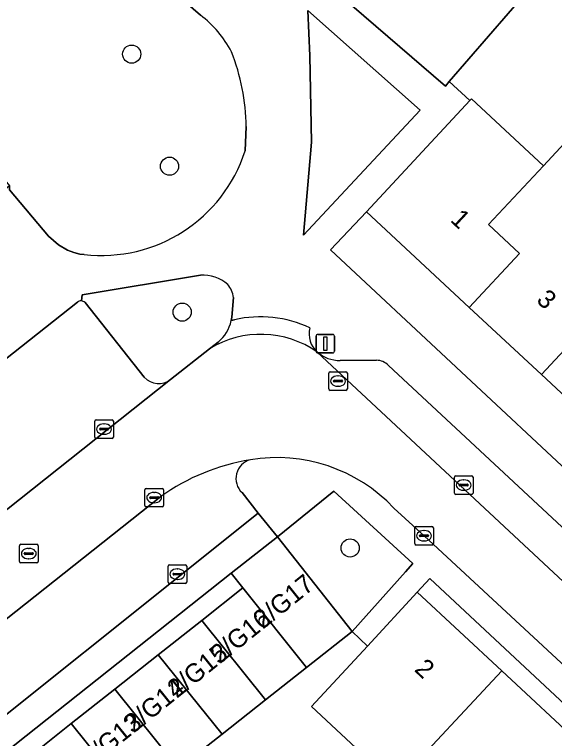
# Model space of a CAD drawing. Extents: x 162344 to 162869, y 381217 to 381818.
# Drawn here: x 162525.97 to 162555.05, y 381693.96 to 381732.95 of the extents above; entities that cross this region are included whole.
import ezdxf

# ---------------------------------------------------------------- set-up
doc = ezdxf.new("R2010")
doc.units = 0
for name, color, linetype in [('IMGEO_Boom', 7, 'Continuous'), ('IMGEO_Erf', 7, 'Continuous'), ('IMGEO_Groenvoorziening', 7, 'Continuous'), ('IMGEO_Kolk', 7, 'Continuous'), ('IMGEO_Lichtmast', 7, 'Continuous'), ('IMGEO_Pand', 7, 'Continuous'), ('IMGEO_Pand_nummerreeks', 7, 'Continuous'), ('IMGEO_Parkeervlak_open', 7, 'Continuous'), ('IMGEO_Rijbaan_lokaal_open', 7, 'Continuous'), ('IMGEO_Rioolput', 7, 'Continuous'), ('IMGEO_Voetpad_open', 7, 'Continuous')]:
    doc.layers.add(name, color=color, linetype=linetype)

msp = doc.modelspace()

# ---------------------------------------------------------------- linework, layer by layer
at = {"layer": 'IMGEO_Boom'}
for centre in [(162532.281, 381730.813), (162534.318, 381724.778), (162535, 381716.921), (162544.045, 381704.221)]:
    msp.add_circle(centre, 0.489, dxfattribs=at)
at = {"layer": 'IMGEO_Erf'}
for points in [[(162535.988, 381732.91), (162527.407, 381740.337), (162531.519, 381745.279), (162534.788, 381749.063), (162535.324, 381749.683), (162537.606, 381747.769), (162539.888, 381745.856), (162542.17, 381743.942), (162544.451, 381742.029), (162546.664, 381740.173), (162550.954, 381736.576), (162551.92, 381735.702), (162553.619, 381734.234), (162549.382, 381729.332), (162550.499, 381728.32), (162550.577, 381728.404), (162554.45, 381724.8), (162556.476, 381726.97)], [(162512.168, 381740.102), (162518.981, 381731.851), (162525.696, 381723.717), (162525.707, 381723.511), (162527.801, 381721.016), (162528.341, 381720.543), (162528.826, 381720.252), (162529.167, 381720.123), (162529.489, 381720.046), (162529.724, 381720.026)], [(162538.393, 381725.598), (162538.45, 381726.908)], [(162558.088, 381710.077), (162554.346, 381713.559), (162550.459, 381717.175), (162544.927, 381722.323), (162542.992, 381720.281), (162563.297, 381701.321)], [(162555.476, 381683.106), (162550.927, 381687.341), (162546.49, 381691.473), (162541.97, 381695.681), (162544.973, 381698.927), (162544.148, 381699.726), (162541.703, 381697.791), (162539.492, 381696.043), (162537.149, 381694.189), (162535.306, 381692.731), (162538.276, 381689.5), (162539.852, 381690.979), (162542.943, 381687.685), (162546.276, 381684.134), (162544.711, 381682.665), (162546.747, 381680.449), (162548.3, 381681.923), (162551.41, 381678.647), (162554.71, 381675.17), (162553.057, 381673.602), (162555.205, 381671.414)]]:
    msp.add_lwpolyline(points, dxfattribs=at)
for points in [[(162533.709, 381698.468), (162536.051, 381700.322), (162538.262, 381702.071), (162537.642, 381702.856), (162523.799, 381691.897), (162524.422, 381691.121), (162526.68, 381692.908), (162529.023, 381694.761), (162531.366, 381696.615)], [(162548.344, 381702.569), (162547.662, 381701.832), (162552.208, 381697.599), (162556.645, 381693.468), (162561.194, 381689.233), (162565.777, 381684.966), (162570.32, 381680.736), (162574.872, 381676.499), (162579.382, 381672.299), (162583.891, 381668.101), (162588.442, 381663.864), (162592.919, 381659.696), (162597.312, 381655.606), (162601.823, 381651.406), (162606.458, 381647.09), (162610.852, 381643), (162615.546, 381638.629), (162616.162, 381639.291), (162606.523, 381648.285)]]:
    msp.add_lwpolyline(points, close=True, dxfattribs=at)
for centre, radius, start, end in [((162532.255, 381728.039), 6.137, 28.2561, 52.5372), ((162526.473, 381726.662), 11.98, 1.1781, 20.9444), ((162530.655, 381728.107), 8.134, 263.4255, 342.0363)]:
    msp.add_arc(centre, radius, start, end, dxfattribs=at)
at = {"layer": 'IMGEO_Groenvoorziening'}
for points in [[(162547.81, 381727.798), (162541.758, 381733.154), (162541.879, 381730.723), (162541.969, 381726.066), (162541.541, 381721.067)], [(162543.164, 381707.283), (162540.132, 381704.823), (162544.148, 381699.726), (162547.035, 381702.94), (162547.422, 381703.385)]]:
    msp.add_lwpolyline(points, close=True, dxfattribs=at)
for points in [[(162535.987, 381718.904), (162529.615, 381717.858), (162529.568, 381717.524)], [(162537.637, 381716.462), (162537.667, 381716.641), (162537.757, 381717.705)], [(162529.766, 381717.44), (162532.959, 381713.412)], [(162534.376, 381713.298), (162536.476, 381714.949), (162536.94, 381715.31)]]:
    msp.add_lwpolyline(points, dxfattribs=at)
for centre, radius, start, end in [((162536.131, 381716.917), 1.992, 48.5378, 94.1464), ((162536.467, 381717.563), 1.298, 6.2969, 40.7656), ((162529.556, 381717.221), 0.303, 46.2549, 87.7676), ((162535.642, 381716.882), 2.038, 309.5387, 348.1105), ((162533.73, 381714.127), 1.051, 222.8426, 307.9582)]:
    msp.add_arc(centre, radius, start, end, dxfattribs=at)
at = {"layer": 'IMGEO_Kolk'}
for p, q in [((162530.293, 381710.194), (162530.293, 381711.046)), ((162530.368, 381711.12), (162531.22, 381711.12)), ((162530.781, 381710.9), (162530.806, 381710.9)), ((162531.294, 381711.046), (162531.294, 381710.194)), ((162530.552, 381710.614), (162530.552, 381710.626)), ((162530.99, 381710.577), (162530.592, 381710.577)), ((162530.595, 381710.663), (162530.993, 381710.663)), ((162531.036, 381710.626), (162531.036, 381710.614)), ((162531.22, 381710.12), (162530.368, 381710.12)), ((162530.804, 381710.34), (162530.779, 381710.34)), ((162549.661, 381707.18), (162549.661, 381708.032)), ((162549.736, 381708.106), (162550.588, 381708.106)), ((162550.149, 381707.886), (162550.174, 381707.886)), ((162550.662, 381708.032), (162550.662, 381707.18)), ((162533.066, 381707.431), (162533.918, 381707.431)), ((162549.92, 381707.6), (162549.92, 381707.612)), ((162550.358, 381707.563), (162549.96, 381707.563)), ((162549.963, 381707.649), (162550.361, 381707.649)), ((162550.404, 381707.612), (162550.404, 381707.6)), ((162532.991, 381706.505), (162532.991, 381707.357)), ((162533.479, 381707.211), (162533.504, 381707.211)), ((162533.992, 381707.357), (162533.992, 381706.505)), ((162550.588, 381707.106), (162549.736, 381707.106)), ((162550.172, 381707.326), (162550.147, 381707.326)), ((162533.25, 381706.925), (162533.25, 381706.937)), ((162533.688, 381706.888), (162533.29, 381706.888)), ((162533.293, 381706.974), (162533.691, 381706.974)), ((162533.502, 381706.651), (162533.477, 381706.651)), ((162533.734, 381706.937), (162533.734, 381706.925)), ((162533.918, 381706.431), (162533.066, 381706.431)), ((162547.526, 381704.453), (162547.526, 381705.305)), ((162547.601, 381705.379), (162548.453, 381705.379)), ((162548.014, 381705.159), (162548.039, 381705.159)), ((162548.527, 381705.305), (162548.527, 381704.453)), ((162547.785, 381704.873), (162547.785, 381704.885)), ((162548.223, 381704.836), (162547.825, 381704.836)), ((162547.828, 381704.922), (162548.226, 381704.922)), ((162548.269, 381704.885), (162548.269, 381704.873)), ((162548.453, 381704.379), (162547.601, 381704.379)), ((162548.037, 381704.599), (162548.012, 381704.599)), ((162534.243, 381702.384), (162534.243, 381703.236)), ((162534.318, 381703.31), (162535.17, 381703.31)), ((162535.244, 381703.236), (162535.244, 381702.384)), ((162534.502, 381702.804), (162534.502, 381702.816)), ((162534.94, 381702.767), (162534.542, 381702.767)), ((162534.545, 381702.853), (162534.943, 381702.853)), ((162534.731, 381703.09), (162534.756, 381703.09)), ((162534.986, 381702.816), (162534.986, 381702.804)), ((162534.754, 381702.53), (162534.729, 381702.53)), ((162535.17, 381702.31), (162534.318, 381702.31))]:
    msp.add_line(p, q, dxfattribs=at)
for points in [[(162530.293, 381710.194), (162530.293, 381711.046)], [(162530.368, 381711.12), (162531.22, 381711.12)], [(162531.294, 381711.046), (162531.294, 381710.194)], [(162531.22, 381710.12), (162530.368, 381710.12)], [(162549.661, 381707.18), (162549.661, 381708.032)], [(162549.736, 381708.106), (162550.588, 381708.106)], [(162550.662, 381708.032), (162550.662, 381707.18)], [(162533.066, 381707.431), (162533.918, 381707.431)], [(162532.991, 381706.505), (162532.991, 381707.357)], [(162533.992, 381707.357), (162533.992, 381706.505)], [(162550.588, 381707.106), (162549.736, 381707.106)], [(162533.918, 381706.431), (162533.066, 381706.431)], [(162547.526, 381704.453), (162547.526, 381705.305)], [(162547.601, 381705.379), (162548.453, 381705.379)], [(162548.527, 381705.305), (162548.527, 381704.453)], [(162548.453, 381704.379), (162547.601, 381704.379)], [(162534.243, 381702.384), (162534.243, 381703.236)], [(162534.318, 381703.31), (162535.17, 381703.31)], [(162535.244, 381703.236), (162535.244, 381702.384)], [(162535.17, 381702.31), (162534.318, 381702.31)]]:
    msp.add_lwpolyline(points, dxfattribs=at)
for centre, radius, start, end in [((162530.37, 381711.044), 0.0765, 91.552, 178.448), ((162530.37, 381711.044), 0.0765, 91.552, 178.448), ((162531.218, 381711.044), 0.0765, 1.552, 88.448), ((162531.218, 381711.044), 0.0765, 1.552, 88.448), ((162530.592, 381710.623), 0.0403, 85.8775, 175.7526), ((162530.589, 381710.613), 0.0366, 178.938, 274.7102), ((162530.993, 381710.62), 0.043, 264.8664, 352.4533), ((162530.997, 381710.625), 0.0386, 1.7309, 96.639), ((162530.37, 381710.196), 0.0765, 181.552, 268.448), ((162530.37, 381710.196), 0.0765, 181.552, 268.448), ((162531.218, 381710.196), 0.0765, 271.552, 358.448), ((162531.218, 381710.196), 0.0765, 271.552, 358.448), ((162549.738, 381708.03), 0.0765, 91.552, 178.448), ((162549.738, 381708.03), 0.0765, 91.552, 178.448), ((162550.586, 381708.03), 0.0765, 1.552, 88.448), ((162550.586, 381708.03), 0.0765, 1.552, 88.448), ((162533.068, 381707.355), 0.0765, 91.552, 178.448), ((162533.068, 381707.355), 0.0765, 91.552, 178.448), ((162533.916, 381707.355), 0.0765, 1.552, 88.448), ((162533.916, 381707.355), 0.0765, 1.552, 88.448), ((162549.96, 381707.609), 0.0403, 85.8775, 175.7526), ((162549.957, 381707.599), 0.0366, 178.938, 274.7102), ((162550.361, 381707.606), 0.043, 264.8664, 352.4533), ((162550.365, 381707.611), 0.0386, 1.7309, 96.639), ((162549.738, 381707.182), 0.0765, 181.552, 268.448), ((162549.738, 381707.182), 0.0765, 181.552, 268.448), ((162550.586, 381707.182), 0.0765, 271.552, 358.448), ((162550.586, 381707.182), 0.0765, 271.552, 358.448), ((162533.29, 381706.934), 0.0403, 85.8775, 175.7526), ((162533.287, 381706.924), 0.0366, 178.938, 274.7102), ((162533.691, 381706.931), 0.043, 264.8664, 352.4533), ((162533.695, 381706.936), 0.0386, 1.7309, 96.639), ((162533.068, 381706.507), 0.0765, 181.552, 268.448), ((162533.068, 381706.507), 0.0765, 181.552, 268.448), ((162533.916, 381706.507), 0.0765, 271.552, 358.448), ((162533.916, 381706.507), 0.0765, 271.552, 358.448), ((162547.603, 381705.303), 0.0765, 91.552, 178.448), ((162547.603, 381705.303), 0.0765, 91.552, 178.448), ((162548.451, 381705.303), 0.0765, 1.552, 88.448), ((162548.451, 381705.303), 0.0765, 1.552, 88.448), ((162547.825, 381704.882), 0.0403, 85.8775, 175.7526), ((162547.822, 381704.872), 0.0366, 178.938, 274.7102), ((162548.226, 381704.879), 0.043, 264.8664, 352.4533), ((162548.23, 381704.884), 0.0386, 1.7309, 96.639), ((162547.603, 381704.455), 0.0765, 181.552, 268.448), ((162547.603, 381704.455), 0.0765, 181.552, 268.448), ((162548.451, 381704.455), 0.0765, 271.552, 358.448), ((162548.451, 381704.455), 0.0765, 271.552, 358.448), ((162534.32, 381703.234), 0.0765, 91.552, 178.448), ((162534.32, 381703.234), 0.0765, 91.552, 178.448), ((162535.168, 381703.234), 0.0765, 1.552, 88.448), ((162535.168, 381703.234), 0.0765, 1.552, 88.448), ((162534.542, 381702.813), 0.0403, 85.8775, 175.7526), ((162534.539, 381702.803), 0.0366, 178.938, 274.7102), ((162534.943, 381702.81), 0.043, 264.8664, 352.4533), ((162534.947, 381702.815), 0.0386, 1.7309, 96.639), ((162534.32, 381702.386), 0.0765, 181.552, 268.448), ((162534.32, 381702.386), 0.0765, 181.552, 268.448), ((162535.168, 381702.386), 0.0765, 271.552, 358.448), ((162535.168, 381702.386), 0.0765, 271.552, 358.448)]:
    msp.add_arc(centre, radius, start, end, dxfattribs=at)
for centre, major_axis, ratio, start_param, end_param in [((162530.78, 381710.62), (-0.387, 0.002), 0.722429, 4.712389, 7.853982), ((162530.805, 381710.62), (-0.39, 0.002), 0.717154, 1.570796, 4.712389), ((162550.148, 381707.606), (-0.387, 0.002), 0.722429, 4.712389, 7.853982), ((162550.173, 381707.606), (-0.39, 0.002), 0.717154, 1.570796, 4.712389), ((162533.478, 381706.931), (-0.387, 0.002), 0.722429, 4.712389, 7.853982), ((162533.503, 381706.931), (-0.39, 0.002), 0.717154, 1.570796, 4.712389), ((162548.013, 381704.879), (-0.387, 0.002), 0.722429, 4.712389, 7.853982), ((162548.038, 381704.879), (-0.39, 0.002), 0.717154, 1.570796, 4.712389), ((162534.73, 381702.81), (-0.387, 0.002), 0.722429, 4.712389, 7.853982), ((162534.755, 381702.81), (-0.39, 0.002), 0.717154, 1.570796, 4.712389)]:
    msp.add_ellipse(centre, major_axis=major_axis, ratio=ratio, start_param=start_param, end_param=end_param, dxfattribs=at)
at = {"layer": 'IMGEO_Lichtmast'}
for p, q in [((162542.211, 381714.82), (162542.211, 381715.62)), ((162542.211, 381715.62), (162542.211, 381714.82)), ((162542.311, 381715.72), (162543.101, 381715.72)), ((162543.101, 381715.72), (162542.311, 381715.72)), ((162543.201, 381715.62), (162543.201, 381714.82)), ((162543.201, 381714.82), (162543.201, 381715.62)), ((162543.101, 381714.72), (162542.311, 381714.72)), ((162542.311, 381714.72), (162543.101, 381714.72))]:
    msp.add_line(p, q, dxfattribs=at)
msp.add_lwpolyline([(162542.631, 381715.595), (162542.781, 381715.595), (162542.781, 381714.845), (162542.631, 381714.845), (162542.631, 381715.595)], dxfattribs=at)
for centre, start, end in [((162542.311, 381715.62), 90, 180), ((162542.311, 381715.62), 90, 180), ((162543.101, 381715.62), 0, 90), ((162543.101, 381715.62), 360, 90), ((162542.311, 381714.82), 180, 270), ((162542.311, 381714.82), 180, 270), ((162543.101, 381714.82), 270, 0), ((162543.101, 381714.82), 270, 0)]:
    msp.add_arc(centre, 0.1, start, end, dxfattribs=at)
at = {"layer": 'IMGEO_Pand'}
for points in [[(162551.92, 381735.702), (162550.954, 381736.576), (162546.664, 381740.173), (162542.783, 381735.545), (162542.325, 381735.015), (162549.177, 381729.094), (162549.382, 381729.332), (162553.619, 381734.234)], [(162554.45, 381724.8), (162550.577, 381728.404), (162550.499, 381728.32), (162544.927, 381722.323), (162550.459, 381717.175), (162553.161, 381720.07), (162551.49, 381721.63)], [(162560.009, 381719.627), (162559.819, 381719.804), (162561.841, 381721.977), (162556.476, 381726.97), (162554.45, 381724.8), (162551.49, 381721.63), (162553.161, 381720.07), (162550.459, 381717.175), (162554.346, 381713.559)], [(162565.324, 381714.682), (162560.009, 381719.627), (162554.346, 381713.559), (162558.088, 381710.077), (162560.779, 381712.96), (162562.349, 381711.494)], [(162540.132, 381704.823), (162537.642, 381702.856), (162538.262, 381702.071), (162541.703, 381697.791), (162544.148, 381699.726)], [(162538.262, 381702.071), (162536.051, 381700.322), (162539.492, 381696.043), (162541.703, 381697.791)], [(162552.208, 381697.599), (162547.662, 381701.832), (162544.973, 381698.927), (162541.97, 381695.681), (162546.49, 381691.473)], [(162536.051, 381700.322), (162533.709, 381698.468), (162537.149, 381694.189), (162539.492, 381696.043)], [(162533.709, 381698.468), (162531.366, 381696.615), (162534.807, 381692.336), (162535.306, 381692.731), (162537.149, 381694.189)], [(162556.645, 381693.468), (162552.208, 381697.599), (162546.49, 381691.473), (162550.927, 381687.341)], [(162531.366, 381696.615), (162529.023, 381694.761), (162532.464, 381690.482), (162534.807, 381692.336)], [(162529.023, 381694.761), (162526.68, 381692.908), (162530.121, 381688.629), (162532.464, 381690.482)]]:
    msp.add_lwpolyline(points, close=True, dxfattribs=at)
at = {"layer": 'IMGEO_Parkeervlak_open'}
for points in [[(162529.359, 381717.448), (162521.93, 381711.58)], [(162532.959, 381713.412), (162529.766, 381717.44)], [(162542.273, 381714.77), (162580.185, 381679.418), (162591.19, 381669.184), (162593.726, 381666.826), (162618.042, 381644.213), (162632.252, 381630.976)], [(162545.457, 381714.327), (162543.509, 381714.316)], [(162581.635, 381680.986), (162546.116, 381714.053)], [(162524.911, 381705.794), (162534.376, 381713.298)], [(162533.842, 381706.991), (162517.7, 381694.186)], [(162539.084, 381706.089), (162538.222, 381707.201)], [(162517.937, 381694.149), (162520.357, 381691.127), (162539.084, 381706.089)]]:
    msp.add_lwpolyline(points, dxfattribs=at)
for centre, radius, start, end in [((162529.559, 381717.224), 0.3, 88.2365, 131.7297), ((162529.556, 381717.221), 0.303, 46.2549, 87.7676), ((162543.494, 381716.184), 1.868, 229.1905, 270.4715), ((162545.456, 381713.395), 0.932, 44.9144, 89.9323), ((162533.73, 381714.127), 1.051, 222.8426, 307.9582), ((162540.529, 381697.545), 11.574, 99.2428, 125.2941), ((162538.936, 381707.96), 1.042, 104.7779, 226.7685)]:
    msp.add_arc(centre, radius, start, end, dxfattribs=at)
at = {"layer": 'IMGEO_Rijbaan_lokaal_open'}
for points in [[(162536.476, 381714.949), (162534.376, 381713.298), (162524.911, 381705.794), (162522.199, 381703.639), (162499.727, 381685.849), (162498.226, 381684.626), (162498.069, 381684.526), (162479.74, 381669.953), (162476.682, 381667.526), (162476.099, 381667.062), (162478.985, 381663.489), (162479.173, 381663.648), (162479.827, 381664.177), (162479.911, 381664.241), (162502.297, 381681.971)], [(162546.399, 381706.372), (162548.027, 381704.879), (162560.818, 381693.021), (162573.453, 381681.241), (162574.275, 381680.474), (162586.238, 381669.332), (162588.969, 381666.789), (162591.19, 381669.184), (162580.185, 381679.418), (162542.273, 381714.77)], [(162516.127, 381692.971), (162517.688, 381694.176), (162517.7, 381694.186), (162533.842, 381706.991)]]:
    msp.add_lwpolyline(points, dxfattribs=at)
for centre, radius, start, end in [((162539.238, 381710.429), 5.297, 55.0401, 121.4226), ((162540.529, 381697.545), 11.574, 99.2428, 125.2941), ((162540.102, 381700.426), 8.661, 43.354, 99.5139)]:
    msp.add_arc(centre, radius, start, end, dxfattribs=at)
at = {"layer": 'IMGEO_Rioolput'}
for p, q in [((162542.893, 381712.782), (162542.893, 381713.634)), ((162542.968, 381713.708), (162543.82, 381713.708)), ((162543.894, 381713.634), (162543.894, 381712.782)), ((162543.195, 381713.251), (162543.593, 381713.251)), ((162543.381, 381713.488), (162543.406, 381713.488)), ((162543.152, 381713.202), (162543.152, 381713.214)), ((162543.59, 381713.165), (162543.192, 381713.165)), ((162543.404, 381712.928), (162543.379, 381712.928)), ((162543.636, 381713.214), (162543.636, 381713.202)), ((162543.82, 381712.708), (162542.968, 381712.708)), ((162526.238, 381703.492), (162526.238, 381704.344)), ((162526.313, 381704.418), (162527.165, 381704.418)), ((162527.239, 381704.344), (162527.239, 381703.492)), ((162526.497, 381703.912), (162526.497, 381703.924)), ((162526.935, 381703.875), (162526.537, 381703.875)), ((162526.54, 381703.961), (162526.938, 381703.961)), ((162526.726, 381704.198), (162526.751, 381704.198)), ((162526.981, 381703.924), (162526.981, 381703.912)), ((162526.749, 381703.638), (162526.724, 381703.638)), ((162527.165, 381703.418), (162526.313, 381703.418))]:
    msp.add_line(p, q, dxfattribs=at)
for points in [[(162542.893, 381712.782), (162542.893, 381713.634)], [(162542.968, 381713.708), (162543.82, 381713.708)], [(162543.894, 381713.634), (162543.894, 381712.782)], [(162543.82, 381712.708), (162542.968, 381712.708)], [(162526.238, 381703.492), (162526.238, 381704.344)], [(162526.313, 381704.418), (162527.165, 381704.418)], [(162527.239, 381704.344), (162527.239, 381703.492)], [(162527.165, 381703.418), (162526.313, 381703.418)]]:
    msp.add_lwpolyline(points, dxfattribs=at)
for centre, radius, start, end in [((162542.97, 381713.632), 0.0765, 91.552, 178.448), ((162542.97, 381713.632), 0.0765, 91.552, 178.448), ((162543.818, 381713.632), 0.0765, 1.552, 88.448), ((162543.818, 381713.632), 0.0765, 1.552, 88.448), ((162543.192, 381713.211), 0.0403, 85.8775, 175.7526), ((162543.597, 381713.213), 0.0386, 1.7309, 96.639), ((162543.189, 381713.201), 0.0366, 178.938, 274.7102), ((162543.593, 381713.208), 0.043, 264.8664, 352.4533), ((162542.97, 381712.784), 0.0765, 181.552, 268.448), ((162542.97, 381712.784), 0.0765, 181.552, 268.448), ((162543.818, 381712.784), 0.0765, 271.552, 358.448), ((162543.818, 381712.784), 0.0765, 271.552, 358.448), ((162526.315, 381704.342), 0.0765, 91.552, 178.448), ((162526.315, 381704.342), 0.0765, 91.552, 178.448), ((162527.163, 381704.342), 0.0765, 1.552, 88.448), ((162527.163, 381704.342), 0.0765, 1.552, 88.448), ((162526.537, 381703.921), 0.0403, 85.8775, 175.7526), ((162526.534, 381703.911), 0.0366, 178.938, 274.7102), ((162526.938, 381703.918), 0.043, 264.8664, 352.4533), ((162526.942, 381703.923), 0.0386, 1.7309, 96.639), ((162526.315, 381703.494), 0.0765, 181.552, 268.448), ((162526.315, 381703.494), 0.0765, 181.552, 268.448), ((162527.163, 381703.494), 0.0765, 271.552, 358.448), ((162527.163, 381703.494), 0.0765, 271.552, 358.448)]:
    msp.add_arc(centre, radius, start, end, dxfattribs=at)
for centre, major_axis, ratio, start_param, end_param in [((162543.38, 381713.208), (-0.387, 0.002), 0.722429, 4.712389, 7.853982), ((162543.405, 381713.208), (-0.39, 0.002), 0.717154, 1.570796, 4.712389), ((162526.725, 381703.918), (-0.387, 0.002), 0.722429, 4.712389, 7.853982), ((162526.75, 381703.918), (-0.39, 0.002), 0.717154, 1.570796, 4.712389)]:
    msp.add_ellipse(centre, major_axis=major_axis, ratio=ratio, start_param=start_param, end_param=end_param, dxfattribs=at)
at = {"layer": 'IMGEO_Voetpad_open'}
for points in [[(162546.116, 381714.053), (162581.635, 381680.986), (162619.498, 381645.735), (162631.092, 381634.929), (162631.144, 381634.866), (162633.394, 381635.882), (162633.056, 381636.194), (162622.51, 381646.029), (162564.247, 381700.434), (162563.297, 381701.321), (162542.992, 381720.281), (162544.927, 381722.323), (162550.499, 381728.32), (162549.382, 381729.332), (162549.177, 381729.094), (162542.325, 381735.015), (162542.783, 381735.545), (162540.53, 381737.492), (162538.277, 381739.439), (162536.025, 381741.385), (162533.772, 381743.332), (162531.519, 381745.279), (162527.407, 381740.337), (162535.988, 381732.91)], [(162538.45, 381726.908), (162538.393, 381725.598)], [(162529.724, 381720.026), (162529.489, 381720.046), (162529.167, 381720.123), (162528.826, 381720.252), (162528.341, 381720.543), (162527.801, 381721.016), (162525.707, 381723.511), (162525.696, 381723.717), (162518.63, 381717.886), (162517.837, 381717.246), (162514.818, 381715.325)], [(162529.568, 381717.524), (162529.615, 381717.858), (162535.987, 381718.904)], [(162537.757, 381717.705), (162537.667, 381716.641), (162537.637, 381716.462), (162537.815, 381716.509)], [(162521.93, 381711.58), (162529.359, 381717.448)], [(162537.815, 381716.509), (162537.637, 381716.462)], [(162536.94, 381715.31), (162536.476, 381714.949)], [(162543.509, 381714.316), (162545.457, 381714.327)], [(162538.222, 381707.201), (162539.084, 381706.089), (162540.132, 381704.823), (162543.164, 381707.283), (162547.422, 381703.385), (162547.035, 381702.94), (162544.148, 381699.726), (162544.973, 381698.927), (162547.662, 381701.832), (162548.344, 381702.569), (162606.523, 381648.285), (162616.162, 381639.291), (162615.546, 381638.629), (162616.646, 381637.643), (162618.835, 381635.59), (162624.28, 381630.339)], [(162626.089, 381632.217), (162624.566, 381633.613), (162621.502, 381636.51), (162620.666, 381635.608), (162617.099, 381639.112), (162617.846, 381639.9), (162611.825, 381645.502), (162600.499, 381656.056), (162591.536, 381664.4), (162588.969, 381666.789), (162586.238, 381669.332), (162574.275, 381680.474), (162573.453, 381681.241), (162560.818, 381693.021), (162548.027, 381704.879), (162546.399, 381706.372)]]:
    msp.add_lwpolyline(points, dxfattribs=at)
for points in [[(162541.879, 381730.723), (162541.758, 381733.154), (162547.81, 381727.798), (162541.541, 381721.067), (162541.969, 381726.066)], [(162537.642, 381702.856), (162540.132, 381704.823), (162539.084, 381706.089), (162520.357, 381691.127), (162521.312, 381689.925), (162523.799, 381691.897)]]:
    msp.add_lwpolyline(points, close=True, dxfattribs=at)
for centre, radius, start, end in [((162532.255, 381728.039), 6.137, 28.2561, 52.5372), ((162526.473, 381726.662), 11.98, 1.1781, 20.9444), ((162530.655, 381728.107), 8.134, 263.4255, 342.0363), ((162536.131, 381716.917), 1.992, 48.5378, 94.1464), ((162536.467, 381717.563), 1.298, 6.2969, 40.7656), ((162529.559, 381717.224), 0.3, 88.2365, 131.7297), ((162535.642, 381716.882), 2.038, 309.5387, 348.1105), ((162539.217, 381710.413), 6.255, 64.8465, 102.9534), ((162539.217, 381710.413), 6.255, 64.8465, 102.9534), ((162543.12, 381715.74), 1.288, 164.9425, 228.8986), ((162543.12, 381715.74), 1.288, 164.9425, 228.8986), ((162539.238, 381710.429), 5.297, 55.0401, 121.4226), ((162543.494, 381716.184), 1.868, 229.1905, 270.4715), ((162545.456, 381713.395), 0.932, 44.9144, 89.9323), ((162538.936, 381707.96), 1.042, 104.7779, 226.7685), ((162540.102, 381700.426), 8.661, 43.354, 99.5139)]:
    msp.add_arc(centre, radius, start, end, dxfattribs=at)

# ---------------------------------------------------------------- texts
at = {"layer": 'IMGEO_Pand_nummerreeks'}
for s, rotation, p in [('1', 316.9766, (162549.387, 381721.84)), ('3', 316.9766, (162554.025, 381717.51)), ('2/G17', 38.7778, (162539.346, 381699.817)), ('2/G16', 38.7778, (162537.029, 381697.955)), ('2/G15', 38.7778, (162534.711, 381696.093)), ('2', 316.9766, (162547.457, 381697.625)), ('2/G14', 38.7778, (162532.393, 381694.231)), ('2/G13', 38.7778, (162530.076, 381692.369))]:
    msp.add_text(s, height=1, rotation=rotation, dxfattribs=at).set_placement(p)

doc.saveas('drawing.dxf')
